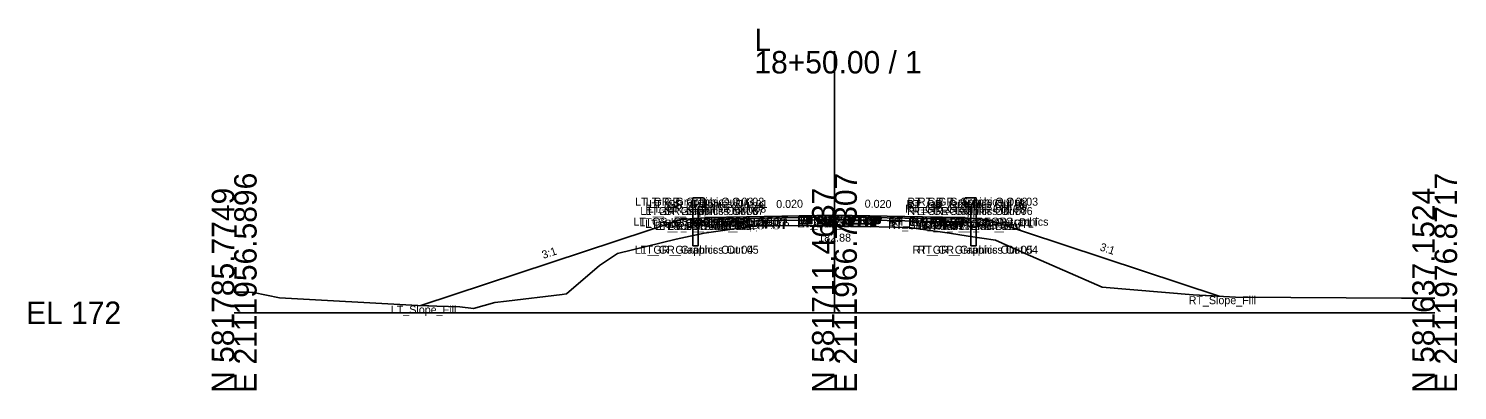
# Model space of a CAD drawing. Extents: x -486 to 1153, y -333 to 9539.
# Drawn here: x -25.7 to 152.8, y 8990.3 to 9035.5 of the extents above; entities that cross this region are included whole.
import ezdxf

# ---------------------------------------------------------------- set-up
doc = ezdxf.new("R2010")
doc.units = 0
for name, color, linetype in [('Default', 7, 'Continuous'), ('Exist Cross Section Cell', 7, 'Continuous'), ('Exist XS Ground Line', 7, 'Continuous'), ('Prop CMT Guardrail Graphics', 7, 'Continuous'), ('Prop CMT Pvmt Course 1', 7, 'Continuous'), ('Prop CMT Pvmt Course 2', 7, 'Continuous'), ('Prop CMT Pvmt Course 3', 7, 'Continuous'), ('Prop CMT Pvmt Surface', 7, 'Continuous'), ('Prop CMT Pvmt Surface Shoulder', 7, 'Continuous'), ('Prop CMT Shld Paved Course 1', 7, 'Continuous'), ('Prop CMT Shld Paved Course 2', 7, 'Continuous'), ('Prop CMT Shld Paved Course 3', 7, 'Continuous'), ('Prop CMT Slope Grass', 7, 'Continuous'), ('Prop CMT Subgrade Earthwork', 7, 'Continuous'), ('Prop XS Earthwork Shape', 7, 'Continuous'), ('Prop XS SE Text', 7, 'Continuous'), ('Prop XS Side Slope Text', 7, 'Continuous'), ('Scratch_Level_0', 7, 'Continuous')]:
    doc.layers.add(name, color=color, linetype=linetype)

msp = doc.modelspace()

# ---------------------------------------------------------------- linework, layer by layer
at = {"layer": 'Exist Cross Section Cell'}
for p, q in [((75, 9000), (75, 9032.68)), ((0, 9000), (75, 9000)), ((75, 9000), (150, 9000))]:
    msp.add_line(p, q, dxfattribs=at)
at = {"layer": 'Exist XS Ground Line'}
for p, q in [((58.73, 9009.95), (65.14, 9010.85)), ((65.14, 9010.85), (67.36, 9010.86)), ((67.36, 9010.86), (74.38, 9010.89)), ((74.38, 9010.89), (75, 9010.88)), ((75, 9010.88), (76.81, 9010.83)), ((76.81, 9010.83), (84.35, 9010.63)), ((84.35, 9010.63), (89.39, 9009.95)), ((47.89, 9007.42), (55.23, 9009.19)), ((55.23, 9009.19), (58.73, 9009.95)), ((89.39, 9009.95), (91.7, 9009.57)), ((91.7, 9009.57), (95.14, 9009.06)), ((95.14, 9009.06), (98.85, 9007.41)), ((45.65, 9005.9), (47.89, 9007.42)), ((98.85, 9007.41), (108.45, 9003.2)), ((41.52, 9002.36), (45.65, 9005.9)), ((0, 9002.57), (1.88, 9002.58)), ((1.88, 9002.58), (2.43, 9002.54)), ((2.43, 9002.54), (5.65, 9001.85)), ((5.65, 9001.85), (22.94, 9000.9)), ((34.01, 9001.45), (40.96, 9002.28)), ((40.96, 9002.28), (41.52, 9002.36)), ((108.45, 9003.2), (119.82, 9002.25)), ((119.82, 9002.25), (125.11, 9001.96)), ((125.11, 9001.96), (145.86, 9001.84)), ((145.86, 9001.84), (150, 9001.82)), ((22.94, 9000.9), (25.3, 9000.83)), ((25.3, 9000.83), (28.21, 9000.76)), ((28.21, 9000.76), (29.89, 9000.52)), ((29.89, 9000.52), (32.58, 9001.27)), ((32.58, 9001.27), (34.01, 9001.45))]:
    msp.add_line(p, q, dxfattribs=at)
at = {"layer": 'Prop CMT Guardrail Graphics'}
for points in [[(57.3, 9008.37), (57.3, 9014.37)], [(57.3, 9014.37), (58.63, 9014.37), (58.9, 9014.08)], [(92.7, 9014.37), (91.37, 9014.37), (91.1, 9014.08)], [(92.7, 9008.37), (92.7, 9014.37)], [(58.9, 9013.5), (58.63, 9013.21), (57.96, 9013.21)], [(57.96, 9013.21), (57.96, 9008.37)], [(58.9, 9014.08), (58.63, 9013.79)], [(58.63, 9013.79), (58.9, 9013.5)], [(91.1, 9014.08), (91.37, 9013.79)], [(91.37, 9013.79), (91.1, 9013.5)], [(91.1, 9013.5), (91.37, 9013.21), (92.04, 9013.21)], [(92.04, 9013.21), (92.04, 9008.37)], [(57.96, 9008.37), (57.3, 9008.37)], [(92.04, 9008.37), (92.7, 9008.37)]]:
    msp.add_lwpolyline(points, dxfattribs=at)
at = {"layer": 'Prop CMT Pvmt Course 1'}
for points in [[(75, 9012.2), (64, 9011.98)], [(64, 9011.77), (75, 9011.99)], [(64, 9011.98), (64, 9011.77)], [(75, 9011.99), (75, 9012.2)], [(75, 9012.2), (86, 9011.98)], [(75, 9011.99), (75, 9012.2)], [(86, 9011.77), (75, 9011.99)], [(86, 9011.98), (86, 9011.77)]]:
    msp.add_lwpolyline(points, dxfattribs=at)
msp.add_lwpolyline([(75, 9011.99), (75, 9012.08), (75, 9012.08), (75, 9011.99)], close=True, dxfattribs=at)
msp.add_lwpolyline([(75, 9011.99), (75, 9012.08), (75, 9012.08), (75, 9011.99)], close=True, dxfattribs=at)
at = {"layer": 'Prop CMT Pvmt Course 2'}
for points in [[(75, 9011.99), (64, 9011.77)], [(64, 9011.77), (64, 9011.44)], [(64, 9011.44), (75, 9011.66)], [(75, 9011.66), (75, 9011.99)], [(75, 9011.66), (75, 9011.99)], [(75, 9011.99), (86, 9011.77)], [(86, 9011.44), (75, 9011.66)], [(86, 9011.77), (86, 9011.44)]]:
    msp.add_lwpolyline(points, dxfattribs=at)
at = {"layer": 'Prop CMT Pvmt Course 3'}
for points in [[(75, 9011.66), (64, 9011.44)], [(64, 9011.44), (64, 9011.44)], [(75, 9011.66), (75, 9011.66)], [(75, 9011.66), (86, 9011.44)], [(75, 9011.66), (75, 9011.66)], [(86, 9011.44), (86, 9011.44)]]:
    msp.add_lwpolyline(points, dxfattribs=at)
at = {"layer": 'Prop CMT Pvmt Surface'}
for points in [[(75, 9012.2), (64, 9011.98)], [(75, 9012.2), (86, 9011.98)]]:
    msp.add_lwpolyline(points, dxfattribs=at)
at = {"layer": 'Prop CMT Pvmt Surface Shoulder'}
for points in [[(64, 9011.98), (59, 9011.88)], [(86, 9011.98), (91, 9011.88)]]:
    msp.add_lwpolyline(points, dxfattribs=at)
at = {"layer": 'Prop CMT Shld Paved Course 1'}
for points in [[(64, 9011.98), (59, 9011.88), (58.79, 9011.67)], [(58.79, 9011.67), (64, 9011.77)], [(64, 9011.77), (64, 9011.98)], [(86, 9011.98), (91, 9011.88), (91.21, 9011.67)], [(86, 9011.77), (86, 9011.98)], [(91.21, 9011.67), (86, 9011.77)]]:
    msp.add_lwpolyline(points, dxfattribs=at)
at = {"layer": 'Prop CMT Shld Paved Course 2'}
for points in [[(64, 9011.77), (58.79, 9011.67), (58.45, 9011.33)], [(58.45, 9011.33), (64, 9011.44)], [(64, 9011.44), (64, 9011.77)], [(86, 9011.77), (91.21, 9011.67), (91.55, 9011.33)], [(86, 9011.44), (86, 9011.77)], [(91.55, 9011.33), (86, 9011.44)]]:
    msp.add_lwpolyline(points, dxfattribs=at)
at = {"layer": 'Prop CMT Shld Paved Course 3'}
for points in [[(64, 9011.44), (58.45, 9011.33)], [(58.45, 9011.33), (58.45, 9011.33), (58.45, 9011.33)], [(64, 9011.44), (64, 9011.44)], [(86, 9011.44), (91.55, 9011.33)], [(86, 9011.44), (86, 9011.44)], [(91.55, 9011.33), (91.55, 9011.33), (91.55, 9011.33)]]:
    msp.add_lwpolyline(points, dxfattribs=at)
at = {"layer": 'Prop CMT Slope Grass'}
for points in [[(55.9, 9011.63), (23.33, 9000.89)], [(58.9, 9011.87), (55.9, 9011.63)], [(59, 9011.88), (58.9, 9011.87)], [(91, 9011.88), (91.1, 9011.87)], [(91.1, 9011.87), (94.1, 9011.63)], [(94.1, 9011.63), (123.09, 9002.07)]]:
    msp.add_lwpolyline(points, dxfattribs=at)
at = {"layer": 'Prop CMT Subgrade Earthwork'}
for points in [[(58.45, 9011.33), (57.98, 9011.8)], [(64, 9011.44), (58.45, 9011.33)], [(75, 9011.66), (64, 9011.44)], [(75, 9011.66), (86, 9011.44)], [(86, 9011.44), (91.55, 9011.33)], [(91.55, 9011.33), (92.02, 9011.8)]]:
    msp.add_lwpolyline(points, dxfattribs=at)
at = {"layer": 'Prop XS Earthwork Shape'}
msp.add_lwpolyline([(55.23, 9009.19), (58.73, 9009.95), (65.14, 9010.85), (67.36, 9010.86), (74.38, 9010.89), (75, 9010.88), (76.81, 9010.83), (84.35, 9010.63), (89.39, 9009.95), (91.7, 9009.57), (95.14, 9009.06), (98.85, 9007.41), (108.45, 9003.2), (119.82, 9002.25), (123.09, 9002.07), (94.1, 9011.63), (92.02, 9011.8), (91.55, 9011.33), (86, 9011.44), (75, 9011.66), (64, 9011.44), (58.45, 9011.33), (57.98, 9011.8), (55.9, 9011.63), (23.33, 9000.89), (25.3, 9000.83), (28.21, 9000.76), (29.89, 9000.52), (32.58, 9001.27), (34.01, 9001.45), (40.96, 9002.28), (41.52, 9002.36), (45.65, 9005.9), (47.89, 9007.42)], close=True, dxfattribs=at)

# ---------------------------------------------------------------- texts
at = {"layer": 'Default'}
for s, height, p in [('182.88', 1, (72.98, 9008.88)), ('-', 0.0001, (0, 9000))]:
    msp.add_text(s, height=height, dxfattribs=at).set_placement(p)
at = {"layer": 'Exist Cross Section Cell'}
for s, p in [('L', (65, 9032.68)), ('18+50.00 / 1', (65, 9029.88)), ('EL 172', (-26, 8998.6))]:
    msp.add_text(s, height=2.8, dxfattribs=at).set_placement(p)
for s, p in [('E 2111956.5896', (2.8, 8990)), ('E 2111966.7307', (77.8, 8990)), ('E 2111976.8717', (152.8, 8990)), ('N 581785.7749', (0, 8990)), ('N 581711.4637', (75, 8990)), ('N 581637.1524', (150, 8990))]:
    msp.add_text(s, height=2.8, rotation=90, dxfattribs=at).set_placement(p)
at = {"layer": 'Prop XS SE Text'}
for rotation, p in [(1.1458, (67.73, 9013.06)), (358.8542, (78.77, 9013.13))]:
    msp.add_text('0.020', height=1, rotation=rotation, dxfattribs=at).set_placement(p)
at = {"layer": 'Prop XS Side Slope Text'}
for rotation, p in [(18.2629, (38.63, 9006.72)), (341.7371, (108.08, 9007.81))]:
    msp.add_text('3:1', height=1, rotation=rotation, dxfattribs=at).set_placement(p)
at = {"layer": 'Scratch_Level_0'}
for s, p in [('LT_GR_Graphics Out 03', (50.08, 9013.37)), ('LT_GR_Graphics Out 02', (51.43, 9013.37)), ('LT_GR_Graphics Out 01', (51.85, 9013.08)), ('RT_GR_Graphics Out 01', (83.99, 9013.08)), ('RT_GR_Graphics Out 02', (84.11, 9013.37)), ('RT_GR_Graphics Out 03', (85.43, 9013.37)), ('LT_GR_Graphics Out 06', (50.74, 9012.21)), ('LT_GR_Graphics Out 07', (51.39, 9012.21)), ('LT_GR_Graphics Out 09', (51.4, 9012.79)), ('LT_GR_Graphics Out 08', (51.67, 9012.5)), ('RT_GR_Graphics Out 08', (83.81, 9012.5)), ('RT_GR_Graphics Out 07', (84.07, 9012.21)), ('RT_GR_Graphics Out 09', (84.09, 9012.79)), ('RT_GR_Graphics Out 06', (84.75, 9012.21)), ('LT_GS_OS_GR_Face_Graphics', (49.9, 9010.87)), ('LT_Sub_Trench_Out_DLT', (50.63, 9010.8)), ('LT_GS_OS_CTL', (51.36, 9010.63)), ('LT_Sub_Trench_Out', (52.56, 9010.33)), ('LT_PS3_Shelf_Out', (53.1, 9010.33)), ('LT_PS3_OEOP', (54.23, 9010.33)), ('LT_PS2_OEOP', (54.57, 9010.67)), ('LT_PS1_OEOP', (54.91, 9010.88)), ('LT_PV2_OEOT', (59.75, 9010.77)), ('LT_PV3_OEOT', (59.75, 9010.44)), ('LT_Sub_OEOT', (59.77, 9010.44)), ('LT_PV1_OEOT', (59.87, 9010.98)), ('RT_PV2_OEEOP', (70.33, 9010.99)), ('RT_PV3_OEEOP', (70.33, 9010.66)), ('RT_Sub_OEEOP', (70.36, 9010.66)), ('LT_PV2_OEEOP', (70.39, 9010.99)), ('LT_PV3_OEEOP', (70.39, 9010.66)), ('LT_Sub_OEEOP', (70.42, 9010.66)), ('RT_PV1_OEEOP', (70.45, 9011.08)), ('LT_PV1_OEEOP', (70.51, 9011.08)), ('RT_PV2_IEEOP', (70.71, 9010.99)), ('LT_PV2_IEEOP', (70.77, 9010.99)), ('RT_PV1_IEEOP', (70.83, 9011.08)), ('LT_PV1_IEEOP', (70.89, 9011.08)), ('PV2_PGL', (72.35, 9010.99)), ('PV1_PGL', (72.47, 9011.2)), ('RT_PV2_OEOT', (81.69, 9010.77)), ('RT_PV3_OEOT', (81.69, 9010.44)), ('RT_Sub_OEOT', (81.71, 9010.44)), ('RT_PV1_OEOT', (81.81, 9010.98)), ('RT_GS_OS_GR_Face_Graphics', (82.04, 9010.87)), ('RT_Sub_Trench_Out_DLT', (84.61, 9010.8)), ('RT_Sub_Trench_Out', (85.6, 9010.33)), ('RT_PS3_Shelf_Out', (86.15, 9010.33)), ('RT_PS1_OEOP', (86.85, 9010.88)), ('RT_PS2_OEOP', (86.94, 9010.67)), ('RT_PS3_OEOP', (87.28, 9010.33)), ('RT_GS_OS_CTL', (89.5, 9010.63)), ('LT_GR_Graphics Out 04', (50.07, 9007.37)), ('LT_GR_Graphics Out 05', (50.74, 9007.37)), ('RT_GR_Graphics Out 05', (84.76, 9007.37)), ('RT_GR_Graphics Out 04', (85.41, 9007.37)), ('RT_Slope_Fill', (119.26, 9001.07)), ('LT_Slope_Fill', (19.57, 8999.89))]:
    msp.add_text(s, height=1, dxfattribs=at).set_placement(p)

doc.saveas('drawing.dxf')
